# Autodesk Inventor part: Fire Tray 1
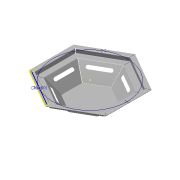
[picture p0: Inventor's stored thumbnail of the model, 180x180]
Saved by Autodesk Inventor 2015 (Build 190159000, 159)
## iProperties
Created: 2013-06
Part Number: Fire Tray 1
Material: Steel, Mild
Document SubType Name: Sheet Metal
Designer: 1103005
Density: 1 g/cm^3
Flat Pattern Width: 60.4665 cm
Flat Pattern Length: 66.3537 cm
Flat Pattern Area: 4012.17 cm^2
Sheet Metal Rule: Default_mm
Sheet Metal Width: 604.665 mm
Sheet Metal Length: 663.537 mm
Sheet Metal Area: 401217.201 mm^2
Appearance: Steel
Author: 1103005
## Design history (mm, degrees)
node "Face1"
node "Contour Flange1"
sketch "Sketch3"
  geometry: L1 (50, 30.306)-(158.045, 30.306); L2 (50, 20.306)-(158.045, 20.306); L3 (158.045, 40.306)-(50, 40.306); A1 r 10 centre (50, 30.306) between (50, 40.306) and (50, 20.306); A2 r 10 centre (158.045, 30.306) between (158.045, 20.306) and (158.045, 40.306); 4 further points
  constraints: 8 end point, 4 point on circle, 4 tangent, 2 centre point, 1 midpoint, 1 parallel
  dimensions: "d19" = 50 horizontal distance of point (0, 0) L1.start; "d20" = 50 horizontal distance of point (208.045, 0) L1.end; "d21" = 10 distance from line of L3 L1.start
cut "Cut1" sketch "Sketch3" dims "d22" = 2 (= Thickness), "d23" = 0
pattern_circular "Circular Pattern1" dims angle "d25" = 360 deg
sketch "Sketch5"
  geometry: L1 (0, 0)-(-242.282, 139.882) reference; L2 (-242.282, 139.882)-(-219.282, 153.161) reference; L3 (0, 26.558)-(0, 0) reference; L4 (-230.782, 146.521)-(0, 13.279); 5 further points
  constraints: 3 midpoint, 2 end point, 1 coincident, 4 other
  dimensions: "d39" = 360 deg dimension on point (1, 281.495) point (-115.391, 79.9) (derived)
node "Hole1"
node "Hole4"
node "Hole6"
body "Solid1"
sketch "Sketch1"
  geometry: L1 (-115, 66.395)-(0, 132.791); L2 (0, 132.791)-(115, 66.395); L3 (115, 66.395)-(115, -66.395); L4 (115, -66.395)-(0, -132.791); L5 (0, -132.791)-(-115, -66.395); L6 (-115, -66.395)-(-115, 66.395); 3 further points
  constraints: 12 end point, 1 coincident, 1 vertical, 13 other
  dimensions: "d0" = 230 distance between parallel lines of L3 L6
face "Plate1" dims "Thickness" = 2
sketch "Sketch2"
  geometry: L1 (0, 0)-(-115, 0); L2 (-115, 0)-(-184.282, 80); L3 (-184.282, 80)-(-219.282, 80); L4 (-219.282, 80)-(-219.282, 105); L5 (-219.282, 105)-(-244.282, 105)
  constraints: 10 end point, 2 horizontal, 1 parallel, 1 perpendicular
  dimensions: "d2" = 115 distance of L1.start L1.end; "d3" = 25 distance of L4.end L5.end; "d4" = 25 distance of L3.end L4.end; "d5" = 35 distance of L2.end L3.end; "d8" = 80 distance between parallel lines of L1 L3; "d18" = 184.28203 horizontal distance of L1.start L2.end (derived)
face "Plate2" dims "d9" = 2 (= BendReliefWidth), "d10" = 1 (= BendReliefDepth), "d11" = 4 (= MinimumRemnant), "d12" = 2 (= BendRadius), "d13" = 2 (= BendRadius), "d14" = 1.2, "d15" = 8 (= CornerReliefSize), "d16" = 2 (= GapSize), "d17" = 2 (= JacobiRadiusSize), "SeamGap" = 0.01, "Thickness" = 2
bend "Bend1" dims "d9" = 2 (= BendReliefWidth), "d10" = 1 (= BendReliefDepth), "d11" = 4 (= MinimumRemnant), "d12" = 2 (= BendRadius), "d13" = 2 (= BendRadius), "d14" = 1.2, "SeamGap" = 0.01, "Thickness" = 2
feature "Corner1" dims "d14" = 1.2, "d15" = 8 (= CornerReliefSize), "d16" = 2 (= GapSize), "d17" = 2 (= JacobiRadiusSize)
sketch "Sketch6"
  geometry: 3 further points
hole "Hole2" sketch "Sketch6" diameter "d41" = 5.5; stored, may be unused: countersink angle "d45" = 90 deg, drill point angle "d47" = 0 deg; dims "d42" = 6, "d43" = 10.4, "d44" = 2, "d46" = 8
sketch "Sketch7"
  geometry: 3 further points
hole "Hole3" sketch "Sketch7" diameter "d48" = 5.5; stored, may be unused: countersink angle "d52" = 90 deg, drill point angle "d54" = 0 deg; dims "d49" = 6, "d50" = 4, "d51" = 2, "d53" = 8
sketch "Sketch8"
  geometry: 3 further points
hole "Hole5" sketch "Sketch8" diameter "d55" = 5.5; stored, may be unused: countersink angle "d59" = 90 deg, drill point angle "d61" = 0 deg; dims "d56" = 6, "d57" = 4, "d58" = 2, "d60" = 8
feature "Definition1"
other parameters: "BendRadius" = 2 (= Thickness), "BendReliefWidth" = 2 (= Thickness), "BendReliefDepth" = 1 (= 0.5 x Thickness), "CornerReliefSize" = 8 (= 4 x Thickness), "MinimumRemnant" = 4 (= 2 x Thickness), "TransitionRadius" = 2 (= BendRadius), "JacobiRadiusSize" = 2 (= BendRadius), "GapSize" = 2 (= Thickness), "d1" = 2 (= BendRadius), "BendRadius" = 2, "BendReliefDepth" = 1, "BendReliefWidth" = 2, "CornerReliefSize" = 8, "GapSize" = 2, "JacobiRadiusSize" = 2, "MinimumRemnant" = 4, "Thickness" = 2, "TransitionRadius" = 2
